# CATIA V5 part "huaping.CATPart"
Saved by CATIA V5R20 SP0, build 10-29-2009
Part number: 花瓶
Material "无"
Material "Bordeaux Red": density 7860 kg/m3, Young's modulus 2e+11 Pa, Poisson ratio 0.266
Material "White Wall": density 2750 kg/m3, Young's modulus 6e+10 Pa, Poisson ratio 0.28
Bounding box of the stored display mesh (mm): x -40 to 40, y -40 to 45.921, z -0.446 to 139.494
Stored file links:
  I:\180212721马可\huaping.CATPart
  G:\catia v20\win_b64\startup\materials\Catalog.CATMaterial
  G:\catia v20\win_b64\startup\materials\turf.jpg
  G:\catia v20\win_b64\startup\materials\bright_oak.jpg
  G:\catia v20\win_b64\startup\materials\fence_1.jpg
  G:\catia v20\win_b64\startup\materials\pinetree.jpg
  G:\catia v20\win_b64\startup\materials\brown_fabric_02.jpg
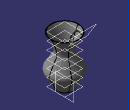
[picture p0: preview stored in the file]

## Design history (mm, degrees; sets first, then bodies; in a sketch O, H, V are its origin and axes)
Set1, material "Bordeaux Red"
  Plane1: type Offset, RefPlane xy-plane, Offset 20
  Plane2: type Offset, RefPlane Plane1, Offset 20
  Plane3: type Offset, RefPlane Plane2, Offset 20
  Plane4: type Offset, RefPlane Plane3, Offset 20
  Plane5: type Offset, RefPlane Plane4, Offset 20
  Plane6: type Offset, RefPlane Plane5, Offset 20
  Sketch1 on Plane2, origin (0, 0, 40), H (1, 0, 0), V (0, 1, 0)
    circle A1 centre (0, 0) radius 40
    radius A1 = 40
  Sketch2 on xy-plane, origin (0, 0, 0), H (1, 0, 0), V (0, 1, 0)
    circle A1 centre (0, 0) radius 20
    radius A1 = 20
  Sketch3 on Plane1, origin (0, 0, 20), H (1, 0, 0), V (0, 1, 0)
    circle A1 centre (0, 0) radius 30
    radius A1 = 30
  Sketch4 on Plane3, origin (0, 0, 60), H (1, 0, 0), V (0, 1, 0)
    circle A1 centre (0, 0) radius 30
    point P1 (30, 0)
    distance P1 V = 30
    radius A1 = 30
    coincidence: A1 P1
  Sketch5 on Plane4, origin (0, 0, 80), H (1, 0, 0), V (0, 1, 0)
    circle A1 centre (0, 0) radius 20
    radius A1 = 20
  Sketch6 on Plane5, origin (0, 0, 100), H (1, 0, 0), V (0, 1, 0)
    circle A1 centre (0, 0) radius 25
    radius A1 = 25
  Sketch7 on Plane6, origin (0, 0, 120), H (1, 0, 0), V (0, 1, 0)
    circle A1 centre (0, 0) radius 35
    radius A1 = 35
Body1 (main body), material "White Wall"
  Loft1: solid, Sections (Sketch2; Sketch3; Sketch1; Sketch4; Sketch5; Sketch6; Sketch7)
  Shell1: IntOffset 1, ExtOffset 0, Face face of Loft1
  Sketch8 on yz-plane, origin (0, 0, 0), H (0, 1, 0), V (0, 0, 1)
    spline S1 through (0, 0) (9.2169, 27.8774) (10.5995, 97.4849) (40.5555, 137.9169) (45.3945, 135.6197)
    point P1 (0, 0)
    coincidence: P1 O
  Plane7: type Normal, Curve Sketch8, RefPoint vertex of Sketch8
  Sketch9 on yz-plane, origin (0, 0, 0), H (0, 1, 0), V (0, 0, 1)
    spline S1 through (0, 40.1874) (34.2885, 40.1874)
    spline S2 through (34.2885, 40.1874) (28.6154, 21.0445) (18.3601, 0)
    line L1 (18.3601, 0) -> (0, 0)
    point P1 (18.3601, 0)
    axis line L2 (0, 1.0315) -> (0, 120.2394)
    point P2 (0, 1.0315)
    point P4 (0, 40.1874)
    point P5 (34.2885, 40.1874)
    point P6 (34.2885, 40.1874)
    point P7 (18.3601, 0)
    coincidence: P4 V, P5 P6, P7 H, P7 P1, P2 V
    horizontal: L1 H
    vertical: L2 V
  Shaft1: profile Sketch9, axis Sketch9.L2, angle 360
  Sketch10 on Plane7, origin (0, -28.9381, 18.3413), H (1, 0, 0), V (0, 0.5353, 0.8446)
    circle A1 centre (0, 138.835) radius 1
    point P1 (0, 138.835)
    radius A1 = 1
    coincidence: P1 V
  Rib1: profile Sketch10, centre curve Sketch8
